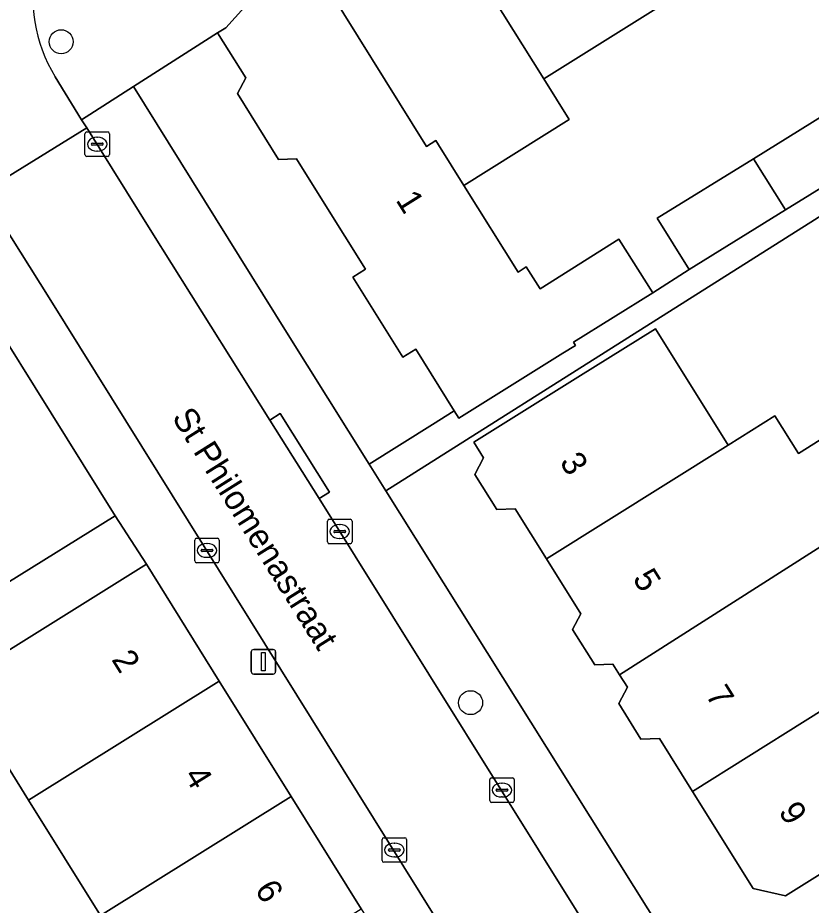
# Model space of a CAD drawing. Extents: x 159664 to 160323, y 385312 to 386115.
# Drawn here: x 160029.84 to 160062.21, y 385549.35 to 385585.55 of the extents above; entities that cross this region are included whole.
import ezdxf

# ---------------------------------------------------------------- set-up
doc = ezdxf.new("R2010")
doc.units = 0
for name, color, linetype in [('IMGEO_Boom', 7, 'Continuous'), ('IMGEO_Erf', 7, 'Continuous'), ('IMGEO_Kolk', 7, 'Continuous'), ('IMGEO_Lichtmast', 7, 'Continuous'), ('IMGEO_Openbare_ruimte_label', 7, 'Continuous'), ('IMGEO_Pand', 7, 'Continuous'), ('IMGEO_Pand_nummerreeks', 7, 'Continuous'), ('IMGEO_Rijbaan_lokaal_open', 7, 'Continuous'), ('IMGEO_Voetpad_open', 7, 'Continuous')]:
    doc.layers.add(name, color=color, linetype=linetype)

msp = doc.modelspace()

# ---------------------------------------------------------------- linework, layer by layer
at = {"layer": 'IMGEO_Boom'}
for centre in [(160031.612, 385584.567), (160048.311, 385557.614)]:
    msp.add_circle(centre, 0.489, dxfattribs=at)
at = {"layer": 'IMGEO_Erf'}
for points in [[(160055.978, 385585.976), (160051.298, 385583.052), (160052.334, 385581.398), (160048.039, 385578.709), (160050.245, 385575.177), (160050.581, 385575.387), (160051.142, 385574.489), (160054.353, 385576.52), (160055.744, 385574.325), (160057.223, 385575.276), (160055.926, 385577.372), (160059.844, 385579.797), (160063.651, 385582.153), (160064.948, 385580.057), (160066.683, 385581.16), (160065.344, 385583.265), (160068.906, 385585.531), (160070.334, 385583.287), (160071.405, 385583.967), (160070.629, 385585.198), (160074.817, 385587.836)], [(160064.959, 385578.961), (160055.905, 385573.241), (160044.854, 385566.259), (160057.315, 385546.366), (160060.924, 385545.652), (160067.311, 385549.981)], [(160070.712, 385555.71), (160061.157, 385549.736), (160059.838, 385550.04), (160057.367, 385553.99), (160056.014, 385556.153), (160055.259, 385556.127), (160054.351, 385557.578), (160054.705, 385558.243), (160054.39, 385558.746), (160054.118, 385559.18), (160053.372, 385559.154), (160052.466, 385560.602), (160052.803, 385561.237), (160051.4, 385563.481), (160050.129, 385565.513), (160049.377, 385565.486), (160048.479, 385566.922), (160048.838, 385567.599), (160048.441, 385568.233), (160052.68, 385570.885), (160055.847, 385572.866), (160058.818, 385568.117), (160060.723, 385569.308), (160061.68, 385567.777), (160062.566, 385568.331)], [(160027.858, 385532.894), (160032.596, 385535.846), (160035.697, 385537.777), (160037.992, 385539.206), (160038.068, 385539.086), (160039.041, 385537.523), (160039.611, 385536.609), (160040.011, 385536.858), (160042.373, 385538.329), (160043.014, 385537.299), (160045.027, 385538.553), (160043.54, 385540.94), (160043.457, 385541.073), (160043.37, 385541.213), (160043.329, 385541.188), (160039.516, 385538.816), (160036.063, 385544.36), (160033.212, 385548.937), (160030.28, 385553.644), (160027.309, 385558.415)]]:
    msp.add_lwpolyline(points, dxfattribs=at)
msp.add_lwpolyline([(160042.344, 385577.985), (160041.216, 385579.791), (160040.476, 385579.765), (160038.799, 385582.451), (160039.139, 385583.09), (160037.993, 385584.925), (160034.566, 385582.74), (160040.804, 385572.724), (160044.173, 385567.346), (160046.758, 385568.96), (160047.644, 385569.513), (160046.073, 385572.03), (160045.545, 385571.7), (160043.502, 385574.969), (160044.024, 385575.295)], close=True, dxfattribs=at)
at = {"layer": 'IMGEO_Kolk'}
for p, q in [((160032.581, 385579.964), (160032.581, 385580.816)), ((160032.656, 385580.89), (160033.508, 385580.89)), ((160033.582, 385580.816), (160033.582, 385579.964)), ((160032.883, 385580.433), (160033.281, 385580.433)), ((160033.069, 385580.67), (160033.094, 385580.67)), ((160032.84, 385580.384), (160032.84, 385580.396)), ((160033.278, 385580.347), (160032.88, 385580.347)), ((160033.092, 385580.11), (160033.067, 385580.11)), ((160033.324, 385580.396), (160033.324, 385580.384)), ((160033.508, 385579.89), (160032.656, 385579.89)), ((160042.473, 385564.168), (160042.473, 385565.02)), ((160042.548, 385565.094), (160043.4, 385565.094)), ((160042.961, 385564.874), (160042.986, 385564.874)), ((160043.474, 385565.02), (160043.474, 385564.168)), ((160042.732, 385564.588), (160042.732, 385564.6)), ((160043.17, 385564.551), (160042.772, 385564.551)), ((160042.775, 385564.637), (160043.173, 385564.637)), ((160043.216, 385564.6), (160043.216, 385564.588)), ((160037.06, 385563.395), (160037.06, 385564.247)), ((160037.135, 385564.321), (160037.987, 385564.321)), ((160038.061, 385564.247), (160038.061, 385563.395)), ((160042.984, 385564.314), (160042.959, 385564.314)), ((160037.319, 385563.815), (160037.319, 385563.827)), ((160037.757, 385563.778), (160037.359, 385563.778)), ((160037.362, 385563.864), (160037.76, 385563.864)), ((160037.548, 385564.101), (160037.573, 385564.101)), ((160037.803, 385563.827), (160037.803, 385563.815)), ((160043.4, 385564.094), (160042.548, 385564.094)), ((160037.571, 385563.541), (160037.546, 385563.541)), ((160037.987, 385563.321), (160037.135, 385563.321)), ((160049.09, 385553.623), (160049.09, 385554.475)), ((160049.165, 385554.549), (160050.017, 385554.549)), ((160050.091, 385554.475), (160050.091, 385553.623)), ((160049.349, 385554.043), (160049.349, 385554.055)), ((160049.787, 385554.006), (160049.389, 385554.006)), ((160049.392, 385554.092), (160049.79, 385554.092)), ((160049.578, 385554.329), (160049.603, 385554.329)), ((160049.833, 385554.055), (160049.833, 385554.043)), ((160049.601, 385553.769), (160049.576, 385553.769)), ((160050.017, 385553.549), (160049.165, 385553.549)), ((160044.701, 385551.178), (160044.701, 385552.03)), ((160044.776, 385552.104), (160045.628, 385552.104)), ((160045.189, 385551.884), (160045.214, 385551.884)), ((160045.702, 385552.03), (160045.702, 385551.178)), ((160044.96, 385551.598), (160044.96, 385551.61)), ((160045.398, 385551.561), (160045, 385551.561)), ((160045.003, 385551.647), (160045.401, 385551.647)), ((160045.444, 385551.61), (160045.444, 385551.598)), ((160045.628, 385551.104), (160044.776, 385551.104)), ((160045.212, 385551.324), (160045.187, 385551.324))]:
    msp.add_line(p, q, dxfattribs=at)
for points in [[(160032.581, 385579.964), (160032.581, 385580.816)], [(160032.656, 385580.89), (160033.508, 385580.89)], [(160033.582, 385580.816), (160033.582, 385579.964)], [(160033.508, 385579.89), (160032.656, 385579.89)], [(160042.473, 385564.168), (160042.473, 385565.02)], [(160042.548, 385565.094), (160043.4, 385565.094)], [(160043.474, 385565.02), (160043.474, 385564.168)], [(160037.06, 385563.395), (160037.06, 385564.247)], [(160037.135, 385564.321), (160037.987, 385564.321)], [(160038.061, 385564.247), (160038.061, 385563.395)], [(160043.4, 385564.094), (160042.548, 385564.094)], [(160037.987, 385563.321), (160037.135, 385563.321)], [(160049.09, 385553.623), (160049.09, 385554.475)], [(160049.165, 385554.549), (160050.017, 385554.549)], [(160050.091, 385554.475), (160050.091, 385553.623)], [(160050.017, 385553.549), (160049.165, 385553.549)], [(160044.701, 385551.178), (160044.701, 385552.03)], [(160044.776, 385552.104), (160045.628, 385552.104)], [(160045.702, 385552.03), (160045.702, 385551.178)], [(160045.628, 385551.104), (160044.776, 385551.104)]]:
    msp.add_lwpolyline(points, dxfattribs=at)
for centre, radius, start, end in [((160032.658, 385580.814), 0.0765, 91.552, 178.448), ((160032.658, 385580.814), 0.0765, 91.552, 178.448), ((160033.506, 385580.814), 0.0765, 1.552, 88.448), ((160033.506, 385580.814), 0.0765, 1.552, 88.448), ((160032.88, 385580.393), 0.0403, 85.8775, 175.7526), ((160033.285, 385580.395), 0.0386, 1.7309, 96.639), ((160032.877, 385580.383), 0.0366, 178.938, 274.7102), ((160033.281, 385580.39), 0.043, 264.8664, 352.4533), ((160032.658, 385579.966), 0.0765, 181.552, 268.448), ((160032.658, 385579.966), 0.0765, 181.552, 268.448), ((160033.506, 385579.966), 0.0765, 271.552, 358.448), ((160033.506, 385579.966), 0.0765, 271.552, 358.448), ((160042.55, 385565.018), 0.0765, 91.552, 178.448), ((160042.55, 385565.018), 0.0765, 91.552, 178.448), ((160043.398, 385565.018), 0.0765, 1.552, 88.448), ((160043.398, 385565.018), 0.0765, 1.552, 88.448), ((160042.772, 385564.597), 0.0403, 85.8775, 175.7526), ((160042.769, 385564.587), 0.0366, 178.938, 274.7102), ((160043.173, 385564.594), 0.043, 264.8664, 352.4533), ((160043.177, 385564.599), 0.0386, 1.7309, 96.639), ((160037.137, 385564.245), 0.0765, 91.552, 178.448), ((160037.137, 385564.245), 0.0765, 91.552, 178.448), ((160037.985, 385564.245), 0.0765, 1.552, 88.448), ((160037.985, 385564.245), 0.0765, 1.552, 88.448), ((160042.55, 385564.17), 0.0765, 181.552, 268.448), ((160042.55, 385564.17), 0.0765, 181.552, 268.448), ((160043.398, 385564.17), 0.0765, 271.552, 358.448), ((160043.398, 385564.17), 0.0765, 271.552, 358.448), ((160037.359, 385563.824), 0.0403, 85.8775, 175.7526), ((160037.356, 385563.814), 0.0366, 178.938, 274.7102), ((160037.76, 385563.821), 0.043, 264.8664, 352.4533), ((160037.764, 385563.826), 0.0386, 1.7309, 96.639), ((160037.137, 385563.397), 0.0765, 181.552, 268.448), ((160037.137, 385563.397), 0.0765, 181.552, 268.448), ((160037.985, 385563.397), 0.0765, 271.552, 358.448), ((160037.985, 385563.397), 0.0765, 271.552, 358.448), ((160049.167, 385554.473), 0.0765, 91.552, 178.448), ((160049.167, 385554.473), 0.0765, 91.552, 178.448), ((160050.015, 385554.473), 0.0765, 1.552, 88.448), ((160050.015, 385554.473), 0.0765, 1.552, 88.448), ((160049.389, 385554.052), 0.0403, 85.8775, 175.7526), ((160049.386, 385554.042), 0.0366, 178.938, 274.7102), ((160049.79, 385554.049), 0.043, 264.8664, 352.4533), ((160049.794, 385554.054), 0.0386, 1.7309, 96.639), ((160049.167, 385553.625), 0.0765, 181.552, 268.448), ((160049.167, 385553.625), 0.0765, 181.552, 268.448), ((160050.015, 385553.625), 0.0765, 271.552, 358.448), ((160050.015, 385553.625), 0.0765, 271.552, 358.448), ((160044.778, 385552.028), 0.0765, 91.552, 178.448), ((160044.778, 385552.028), 0.0765, 91.552, 178.448), ((160045.626, 385552.028), 0.0765, 1.552, 88.448), ((160045.626, 385552.028), 0.0765, 1.552, 88.448), ((160045, 385551.607), 0.0403, 85.8775, 175.7526), ((160044.997, 385551.597), 0.0366, 178.938, 274.7102), ((160045.401, 385551.604), 0.043, 264.8664, 352.4533), ((160045.405, 385551.609), 0.0386, 1.7309, 96.639), ((160044.778, 385551.18), 0.0765, 181.552, 268.448), ((160044.778, 385551.18), 0.0765, 181.552, 268.448), ((160045.626, 385551.18), 0.0765, 271.552, 358.448), ((160045.626, 385551.18), 0.0765, 271.552, 358.448)]:
    msp.add_arc(centre, radius, start, end, dxfattribs=at)
for centre, major_axis, ratio, start_param, end_param in [((160033.068, 385580.39), (-0.387, 0.002), 0.722429, 4.712389, 7.853982), ((160033.093, 385580.39), (-0.39, 0.002), 0.717154, 1.570796, 4.712389), ((160042.96, 385564.594), (-0.387, 0.002), 0.722429, 4.712389, 7.853982), ((160042.985, 385564.594), (-0.39, 0.002), 0.717154, 1.570796, 4.712389), ((160037.547, 385563.821), (-0.387, 0.002), 0.722429, 4.712389, 7.853982), ((160037.572, 385563.821), (-0.39, 0.002), 0.717154, 1.570796, 4.712389), ((160049.577, 385554.049), (-0.387, 0.002), 0.722429, 4.712389, 7.853982), ((160049.602, 385554.049), (-0.39, 0.002), 0.717154, 1.570796, 4.712389), ((160045.188, 385551.604), (-0.387, 0.002), 0.722429, 4.712389, 7.853982), ((160045.213, 385551.604), (-0.39, 0.002), 0.717154, 1.570796, 4.712389)]:
    msp.add_ellipse(centre, major_axis=major_axis, ratio=ratio, start_param=start_param, end_param=end_param, dxfattribs=at)
at = {"layer": 'IMGEO_Lichtmast'}
for p, q in [((160039.365, 385558.883), (160039.365, 385559.683)), ((160039.365, 385559.683), (160039.365, 385558.883)), ((160039.465, 385559.783), (160040.255, 385559.783)), ((160040.255, 385559.783), (160039.465, 385559.783)), ((160040.355, 385559.683), (160040.355, 385558.883)), ((160040.355, 385558.883), (160040.355, 385559.683)), ((160040.255, 385558.783), (160039.465, 385558.783)), ((160039.465, 385558.783), (160040.255, 385558.783))]:
    msp.add_line(p, q, dxfattribs=at)
msp.add_lwpolyline([(160039.785, 385559.658), (160039.935, 385559.658), (160039.935, 385558.908), (160039.785, 385558.908), (160039.785, 385559.658)], dxfattribs=at)
for centre, start, end in [((160039.465, 385559.683), 90, 180), ((160039.465, 385559.683), 90, 180), ((160040.255, 385559.683), 0, 90), ((160040.255, 385559.683), 360, 90), ((160039.465, 385558.883), 180, 270), ((160039.465, 385558.883), 180, 270), ((160040.255, 385558.883), 270, 0), ((160040.255, 385558.883), 270, 0)]:
    msp.add_arc(centre, 0.1, start, end, dxfattribs=at)
at = {"layer": 'IMGEO_Pand'}
for points in [[(160051.298, 385583.052), (160055.978, 385585.976), (160051.355, 385593.361), (160050.788, 385593.007), (160050.106, 385593.37), (160048.659, 385592.467), (160048.685, 385591.744), (160046.652, 385590.474)], [(160046.652, 385590.474), (160046.073, 385590.112), (160045.569, 385590.38), (160044.033, 385589.421), (160044.056, 385588.75), (160042.034, 385587.487), (160046.514, 385580.295), (160046.898, 385580.536), (160047.002, 385580.369), (160048.039, 385578.709), (160052.334, 385581.398), (160051.298, 385583.052)], [(160059.844, 385579.797), (160061.152, 385577.708), (160064.948, 385580.057), (160063.651, 385582.153)], [(160061.152, 385577.708), (160059.844, 385579.797), (160055.926, 385577.372), (160057.223, 385575.276)], [(160020.66, 385573.379), (160023.962, 385568.082), (160025.369, 385568.959), (160029.401, 385562.487), (160033.814, 385565.236), (160026.036, 385577.685), (160020.236, 385574.057)], [(160058.818, 385568.117), (160055.847, 385572.866), (160052.68, 385570.885), (160048.441, 385568.233), (160048.838, 385567.599), (160048.479, 385566.922), (160049.377, 385565.486), (160050.129, 385565.513), (160051.4, 385563.481)], [(160064.525, 385565.196), (160062.566, 385568.331), (160061.68, 385567.777), (160060.723, 385569.308), (160058.818, 385568.117), (160051.4, 385563.481), (160052.803, 385561.237), (160052.466, 385560.602), (160053.372, 385559.154), (160054.118, 385559.18), (160054.39, 385558.746), (160063.534, 385564.576)], [(160063.534, 385564.576), (160054.39, 385558.746), (160054.705, 385558.243), (160054.351, 385557.578), (160055.259, 385556.127), (160056.014, 385556.153), (160057.367, 385553.99), (160066.548, 385559.756), (160066.2, 385560.313), (160065.666, 385561.167)], [(160035.088, 385563.259), (160030.844, 385560.616), (160027.309, 385558.415), (160030.28, 385553.644), (160038.059, 385558.489)], [(160069.093, 385558.297), (160070.367, 385559.094), (160069.698, 385560.162), (160068.991, 385561.29), (160068.644, 385561.845), (160066.2, 385560.313), (160066.548, 385559.756), (160057.367, 385553.99), (160059.838, 385550.04), (160061.157, 385549.736), (160070.712, 385555.71)], [(160038.059, 385558.489), (160030.28, 385553.644), (160033.212, 385548.937), (160040.991, 385553.782)], [(160040.991, 385553.782), (160033.212, 385548.937), (160036.063, 385544.36), (160043.841, 385549.205)]]:
    msp.add_lwpolyline(points, close=True, dxfattribs=at)
msp.add_lwpolyline([(160039.724, 385586.702), (160038.327, 385585.134), (160037.993, 385584.925), (160039.139, 385583.09), (160038.799, 385582.451), (160040.476, 385579.765), (160041.216, 385579.791), (160042.344, 385577.985), (160044.024, 385575.295), (160043.502, 385574.969), (160045.545, 385571.7), (160046.073, 385572.03), (160047.644, 385569.513), (160047.832, 385569.212), (160052.073, 385571.861), (160052.584, 385572.18), (160052.502, 385572.311), (160055.744, 385574.325), (160054.353, 385576.52), (160051.142, 385574.489), (160050.581, 385575.387), (160050.245, 385575.177), (160048.039, 385578.709), (160047.002, 385580.369), (160046.898, 385580.536), (160046.514, 385580.295), (160042.034, 385587.487)], dxfattribs=at)
at = {"layer": 'IMGEO_Rijbaan_lokaal_open'}
msp.add_lwpolyline([(160027.02, 385580.613), (160028.067, 385578.956), (160028.398, 385578.432), (160032.656, 385581.05), (160032.447, 385581.389), (160031.371, 385583.135)], dxfattribs=at)
msp.add_lwpolyline([(160042.133, 385565.934), (160040.122, 385569.139), (160035.309, 385576.808), (160032.656, 385581.05), (160028.398, 385578.432), (160031.12, 385574.121), (160051.907, 385540.783), (160053.601, 385538.126), (160057.837, 385540.766), (160054.085, 385546.799)], close=True, dxfattribs=at)
msp.add_arc((160036.517, 385586.321), 6.052, 122.2211, 211.7605, dxfattribs=at)
at = {"layer": 'IMGEO_Voetpad_open'}
for points in [[(160031.371, 385583.135), (160032.447, 385581.389), (160034.566, 385582.74), (160037.993, 385584.925), (160038.327, 385585.134), (160039.724, 385586.702), (160041.577, 385587.202), (160042.034, 385587.487), (160039.832, 385591.044), (160082.689, 385617.809), (160109.844, 385634.843), (160144.925, 385656.737), (160153.937, 385662.319), (160154.019, 385662.222), (160157.604, 385664.439), (160157.464, 385664.678), (160157.932, 385664.971), (160159.148, 385665.732), (160193.313, 385687.116)], [(160034.566, 385582.74), (160032.447, 385581.389), (160032.656, 385581.05), (160035.309, 385576.808), (160040.122, 385569.139), (160040.545, 385569.404), (160042.553, 385566.194), (160042.133, 385565.934), (160054.085, 385546.799), (160057.837, 385540.766), (160059.073, 385538.853)], [(160072.357, 385554.515), (160067.311, 385549.981), (160060.924, 385545.652), (160057.315, 385546.366), (160044.854, 385566.259), (160044.173, 385567.346), (160040.804, 385572.724), (160034.566, 385582.74)], [(160064.948, 385580.057), (160061.152, 385577.708), (160057.223, 385575.276), (160055.744, 385574.325), (160052.502, 385572.311), (160052.584, 385572.18), (160052.073, 385571.861), (160047.832, 385569.212), (160047.644, 385569.513), (160046.758, 385568.96), (160044.173, 385567.346), (160044.854, 385566.259), (160055.905, 385573.241), (160064.959, 385578.961)], [(160031.12, 385574.121), (160028.398, 385578.432), (160028.067, 385578.956), (160026.036, 385577.685), (160033.814, 385565.236), (160035.088, 385563.259), (160038.059, 385558.489), (160040.991, 385553.782), (160043.841, 385549.205), (160047.294, 385543.662), (160051.594, 385536.758), (160053.732, 385533.435), (160054.445, 385531.102)], [(160055.407, 385535.216), (160053.601, 385538.126), (160051.907, 385540.783), (160031.12, 385574.121)], [(160027.309, 385558.415), (160030.844, 385560.616), (160035.088, 385563.259), (160033.814, 385565.236), (160029.401, 385562.487)]]:
    msp.add_lwpolyline(points, dxfattribs=at)
msp.add_lwpolyline([(160040.122, 385569.139), (160042.133, 385565.934), (160042.553, 385566.194), (160040.545, 385569.404)], close=True, dxfattribs=at)
msp.add_arc((160036.517, 385586.321), 6.052, 122.2211, 211.7605, dxfattribs=at)

# ---------------------------------------------------------------- texts
at = {"layer": 'IMGEO_Openbare_ruimte_label'}
msp.add_text('St Philomenastraat', height=1, rotation=302.1329, dxfattribs=at).set_placement((160036.104, 385569.249))
at = {"layer": 'IMGEO_Pand_nummerreeks'}
for s, rotation, p in [('1', 301.988, (160045.236, 385578.112)), ('3', 302.0635, (160051.919, 385567.429)), ('5', 302.0635, (160054.895, 385562.678)), ('2', 301.9165, (160033.643, 385559.376)), ('7', 302.0625, (160057.871, 385557.927)), ('4', 301.9165, (160036.595, 385554.635)), ('9', 302.0625, (160060.847, 385553.176)), ('6', 301.9165, (160039.486, 385549.993))]:
    msp.add_text(s, height=1, rotation=rotation, dxfattribs=at).set_placement(p)

doc.saveas('drawing.dxf')
